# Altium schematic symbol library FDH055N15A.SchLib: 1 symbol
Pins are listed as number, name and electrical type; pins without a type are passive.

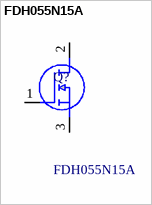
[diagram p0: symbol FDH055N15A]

## FDH055N15A
designator Q?
High Power and Current Handling Capability; Fast Switching Speed; High Performance Trench Technology for Extremely Low RDS(on) ; Low Gate Charge, QG = 92nC ( Typ.); RoHS Compliant; RDS(on) = 4.8m ( Typ.)@ VGS = 10V, ID = 120A; Manufacturer_Name: onsemi; Geometry.Height: 4.82mm
footprint TO556P482X1562X2475-3P
pins: 1 G, 2 D, 3 S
